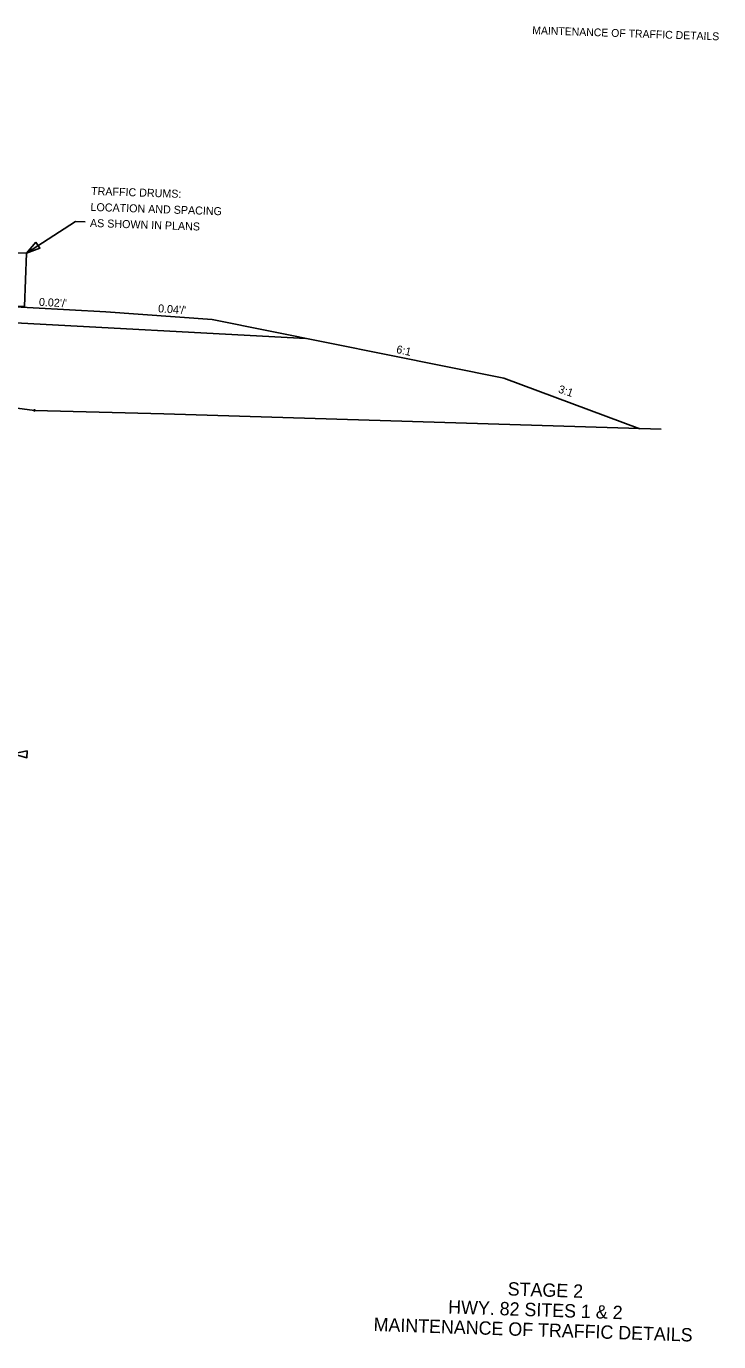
# Model space of a CAD drawing. Extents: x 977258 to 978774, y 1525946 to 1526932.
# Drawn here: x 978255 to 978774, y 1525946 to 1526932 of the extents above; entities that cross this region are included whole.
import ezdxf

# ---------------------------------------------------------------- set-up
doc = ezdxf.new("R2010")
doc.units = 0
for name, color, linetype in [('B_border', 7, 'Continuous'), ('B_Preliminary', 7, 'Continuous'), ('B_Print_Date_Text', 7, 'Continuous'), ('R_Border', 7, 'Continuous'), ('R_Border Prem', 7, 'Continuous'), ('R_MOT', 7, 'Continuous'), ('STAMP_PP', 7, 'Continuous')]:
    doc.layers.add(name, color=color, linetype=linetype)

msp = doc.modelspace()

# ---------------------------------------------------------------- linework, layer by layer
at = {"layer": 'B_border'}
msp.add_circle((978261.1, 1526644), 0.5, dxfattribs=at)
at = {"layer": 'B_Preliminary'}
msp.add_lwpolyline([(978205.08, 1526651.49), (978261.1, 1526644), (978358.12, 1526641.28), (978730.87, 1526629.77)], dxfattribs=at)
at = {"layer": 'B_Print_Date_Text'}
for p, q in [((978314.63, 1526717.86), (978019.99, 1526733.59)), ((978464.53, 1526697.9), (978019.6, 1526721.66)), ((978314.63, 1526717.86), (978394.48, 1526711.99)), ((978394.48, 1526711.99), (978613.14, 1526668.01)), ((978714.96, 1526630.26), (978613.14, 1526668.01))]:
    msp.add_line(p, q, dxfattribs=at)
at = {"layer": 'R_MOT'}
msp.add_lwpolyline([(978233.79, 1526722.41), (978253.78, 1526721.74), (978255.12, 1526761.72), (978235.13, 1526762.38)], close=True, dxfattribs=at)
at = {"layer": 'STAMP_PP'}
for p, q in [((978291.99, 1526785.63), (978255.12, 1526761.72)), ((978299.2, 1526785.38), (978291.99, 1526785.63))]:
    msp.add_line(p, q, dxfattribs=at)
for points in [[(978262.26, 1526769.93), (978255.12, 1526761.72), (978265.28, 1526765.6)], [(978255.67, 1526388.9), (978245.03, 1526386.61), (978255.5, 1526383.62)]]:
    msp.add_lwpolyline(points, close=True, dxfattribs=at)

# ---------------------------------------------------------------- texts
at = {"layer": 'R_Border'}
for s, height, rotation, p in [('TRAFFIC DRUMS:', 6, 358.09005, (978303.49, 1526805.48)), ('LOCATION AND SPACING ', 6, 358.09005, (978303.09, 1526793.49)), ('AS SHOWN IN PLANS', 6, 358.09005, (978302.69, 1526781.49)), ("0.02'/'", 6, 356.94429, (978264.38, 1526722.35)), ("0.04'/'", 6, 355.79944, (978353.65, 1526717.55)), ('6:1', 6, 347.77609, (978532.01, 1526687.08)), ('3:1', 6, 341.32808, (978653.34, 1526657.49)), ('STAGE 2', 10, 358.09005, (978615.82, 1525980.67)), ('HWY. 82 SITES 1 & 2', 10, 358.09005, (978571.17, 1525967.15)), ('MAINTENANCE OF TRAFFIC DETAILS', 10, 358.09005, (978515.27, 1525954.01))]:
    msp.add_text(s, height=height, rotation=rotation, dxfattribs=at).set_placement(p)
at = {"layer": 'R_Border Prem'}
msp.add_text('MAINTENANCE OF TRAFFIC DETAILS', height=5.862, rotation=358.09005, dxfattribs=at).set_placement((978634.24, 1526925.99))

doc.saveas('drawing.dxf')
